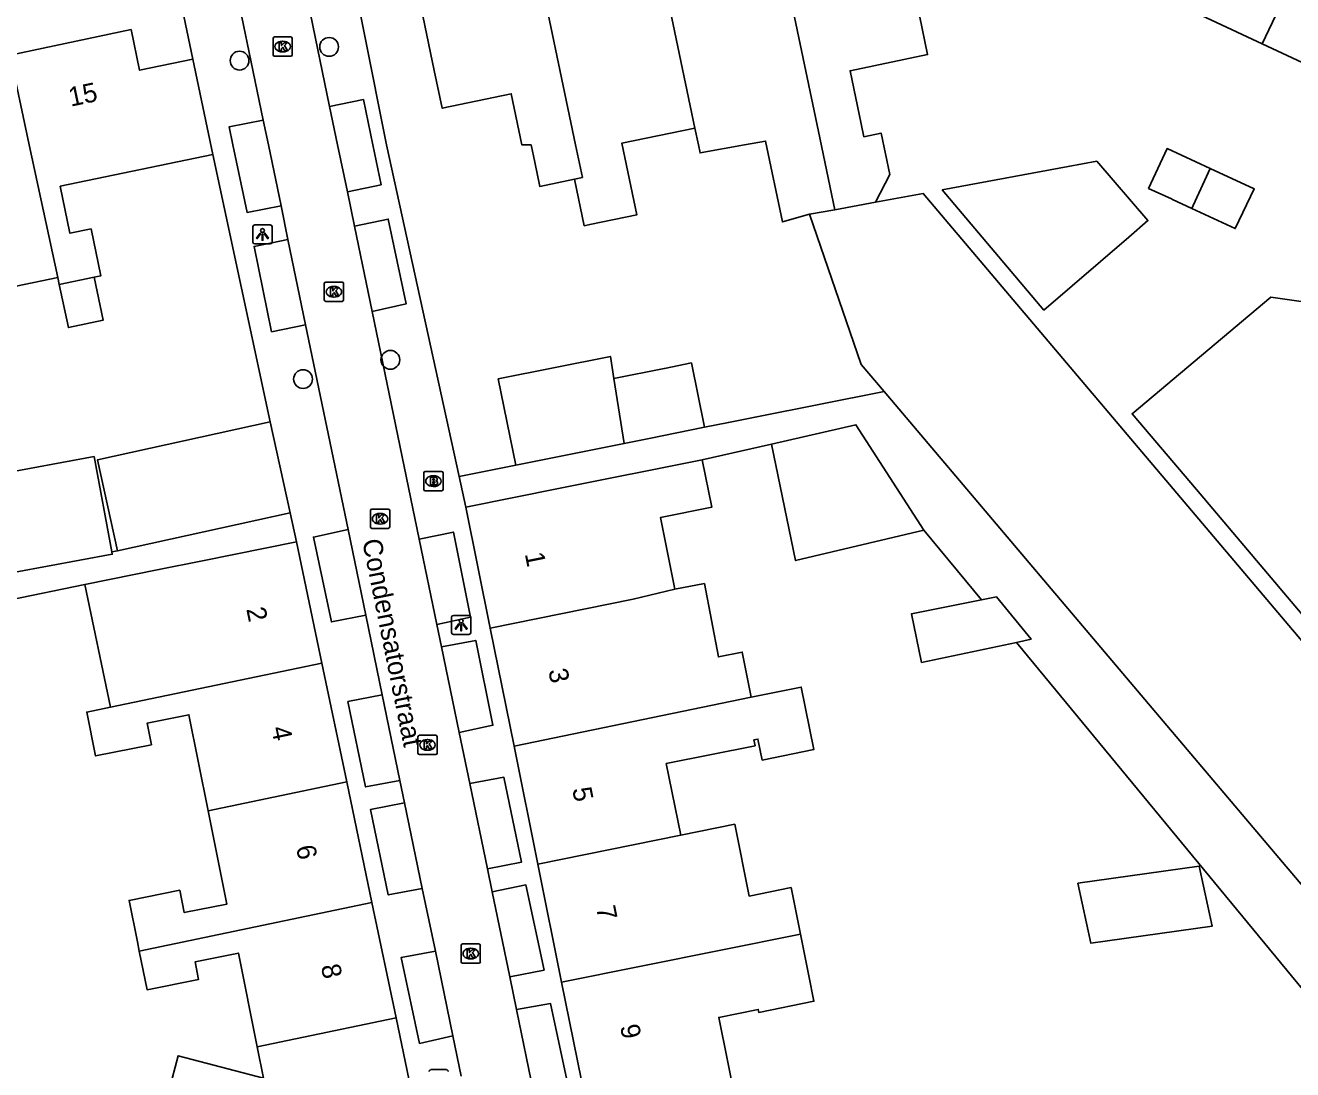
# Model space of a CAD drawing. Extents: x 162990 to 165007, y 383433 to 384336.
# Drawn here: x 163657.2 to 163723.1, y 383951.9 to 384006.2 of the extents above; entities that cross this region are included whole.
import ezdxf

# ---------------------------------------------------------------- set-up
doc = ezdxf.new("R2010")
doc.units = 0
for name, color, linetype in [('IMGEO_Boom', 7, 'Continuous'), ('IMGEO_Brandkraan', 7, 'Continuous'), ('IMGEO_Kolk', 7, 'Continuous'), ('IMGEO_Lichtpunt', 7, 'Continuous'), ('IMGEO_Openbare_ruimte_label', 7, 'Continuous'), ('IMGEO_Pand', 7, 'Continuous'), ('IMGEO_Pand_nummerreeks', 7, 'Continuous'), ('IMGEO_Rijbaan_lokaal_open', 7, 'Continuous'), ('IMGEO_Voetpad_open', 7, 'Continuous')]:
    doc.layers.add(name, color=color, linetype=linetype)

msp = doc.modelspace()

# ---------------------------------------------------------------- linework, layer by layer
at = {"layer": 'IMGEO_Boom'}
for centre in [(163673.01, 384005.098), (163668.353, 384004.381), (163676.194, 383988.817), (163671.653, 383987.815)]:
    msp.add_circle(centre, 0.489, dxfattribs=at)
at = {"layer": 'IMGEO_Brandkraan'}
for p, q in [((163677.934, 383982.078), (163677.934, 383982.93)), ((163678.009, 383983.004), (163678.861, 383983.004)), ((163678.422, 383982.784), (163678.447, 383982.784)), ((163678.935, 383982.93), (163678.935, 383982.078)), ((163678.445, 383982.224), (163678.42, 383982.224)), ((163678.861, 383982.004), (163678.009, 383982.004))]:
    msp.add_line(p, q, dxfattribs=at)
for points in [[(163677.934, 383982.078), (163677.934, 383982.93)], [(163678.009, 383983.004), (163678.861, 383983.004)], [(163678.935, 383982.93), (163678.935, 383982.078)], [(163678.282, 383982.704), (163678.282, 383982.304), (163678.495, 383982.304)], [(163678.513, 383982.704), (163678.282, 383982.704)], [(163678.461, 383982.623), (163678.407, 383982.623), (163678.407, 383982.547)], [(163678.407, 383982.547), (163678.46, 383982.547)], [(163678.469, 383982.471), (163678.407, 383982.471), (163678.407, 383982.39)], [(163678.407, 383982.39), (163678.469, 383982.39)], [(163678.861, 383982.004), (163678.009, 383982.004)]]:
    msp.add_lwpolyline(points, dxfattribs=at)
for centre, radius, start, end in [((163678.011, 383982.928), 0.0765, 91.55205, 178.44795), ((163678.011, 383982.928), 0.0765, 91.55205, 178.44795), ((163678.859, 383982.928), 0.0765, 1.55205, 88.44795), ((163678.859, 383982.928), 0.0765, 1.55205, 88.44795), ((163678.011, 383982.08), 0.0765, 181.55205, 268.44795), ((163678.011, 383982.08), 0.0765, 181.55205, 268.44795), ((163678.462, 383982.585), 0.0379, 267.82845, 90.93552), ((163678.47, 383982.43), 0.0404, 269.87594, 90.50774), ((163678.501, 383982.555), 0.251, 268.66757, 293.53466), ((163678.517, 383982.559), 0.145, 59.4692, 91.53667), ((163678.542, 383982.606), 0.0922, 285.51372, 58.15012), ((163678.547, 383982.414), 0.105, 301.31148, 78.98903), ((163678.859, 383982.08), 0.0765, 271.55205, 358.44795), ((163678.859, 383982.08), 0.0765, 271.55205, 358.44795)]:
    msp.add_arc(centre, radius, start, end, dxfattribs=at)
for centre, major_axis, ratio, start_param, end_param in [((163678.421, 383982.504), (-0.387, 0.002), 0.722429, 4.712389, 7.853982), ((163678.446, 383982.504), (-0.39, 0.002), 0.717154, 1.570796, 4.712389)]:
    msp.add_ellipse(centre, major_axis=major_axis, ratio=ratio, start_param=start_param, end_param=end_param, dxfattribs=at)
at = {"layer": 'IMGEO_Kolk'}
for p, q in [((163670.093, 384004.69), (163670.093, 384005.542)), ((163670.168, 384005.616), (163671.02, 384005.616)), ((163670.581, 384005.396), (163670.606, 384005.396)), ((163671.094, 384005.542), (163671.094, 384004.69)), ((163671.02, 384004.616), (163670.168, 384004.616)), ((163670.604, 384004.836), (163670.579, 384004.836)), ((163672.76, 383991.93), (163672.76, 383992.782)), ((163672.835, 383992.856), (163673.687, 383992.856)), ((163673.248, 383992.636), (163673.273, 383992.636)), ((163673.761, 383992.782), (163673.761, 383991.93)), ((163673.271, 383992.076), (163673.246, 383992.076)), ((163673.687, 383991.856), (163672.835, 383991.856)), ((163675.16, 383980.12), (163675.16, 383980.972)), ((163675.235, 383981.046), (163676.087, 383981.046)), ((163675.648, 383980.826), (163675.673, 383980.826)), ((163676.161, 383980.972), (163676.161, 383980.12)), ((163675.671, 383980.266), (163675.646, 383980.266)), ((163676.087, 383980.046), (163675.235, 383980.046)), ((163677.627, 383968.354), (163677.627, 383969.206)), ((163677.702, 383969.28), (163678.554, 383969.28)), ((163678.115, 383969.06), (163678.14, 383969.06)), ((163678.628, 383969.206), (163678.628, 383968.354)), ((163678.554, 383968.28), (163677.702, 383968.28)), ((163678.138, 383968.5), (163678.113, 383968.5)), ((163679.873, 383957.498), (163679.873, 383958.35)), ((163679.948, 383958.424), (163680.8, 383958.424)), ((163680.874, 383958.35), (163680.874, 383957.498)), ((163680.361, 383958.204), (163680.386, 383958.204)), ((163680.8, 383957.424), (163679.948, 383957.424)), ((163680.384, 383957.644), (163680.359, 383957.644))]:
    msp.add_line(p, q, dxfattribs=at)
for points in [[(163670.093, 384004.69), (163670.093, 384005.542)], [(163670.168, 384005.616), (163671.02, 384005.616)], [(163670.414, 384005.316), (163670.537, 384005.316), (163670.537, 384005.165), (163670.667, 384005.316), (163670.831, 384005.316), (163670.685, 384005.165), (163670.838, 384004.916), (163670.686, 384004.916), (163670.601, 384005.08), (163670.537, 384005.013), (163670.537, 384004.916), (163670.414, 384004.916), (163670.414, 384005.316)], [(163671.094, 384005.542), (163671.094, 384004.69)], [(163671.02, 384004.616), (163670.168, 384004.616)], [(163672.76, 383991.93), (163672.76, 383992.782)], [(163672.835, 383992.856), (163673.687, 383992.856)], [(163673.761, 383992.782), (163673.761, 383991.93)], [(163673.081, 383992.556), (163673.204, 383992.556), (163673.204, 383992.405), (163673.334, 383992.556), (163673.498, 383992.556), (163673.352, 383992.405), (163673.505, 383992.156), (163673.353, 383992.156), (163673.268, 383992.32), (163673.204, 383992.253), (163673.204, 383992.156), (163673.081, 383992.156), (163673.081, 383992.556)], [(163673.687, 383991.856), (163672.835, 383991.856)], [(163675.16, 383980.12), (163675.16, 383980.972)], [(163675.235, 383981.046), (163676.087, 383981.046)], [(163675.481, 383980.746), (163675.604, 383980.746), (163675.604, 383980.595), (163675.734, 383980.746), (163675.898, 383980.746), (163675.752, 383980.595), (163675.905, 383980.346), (163675.753, 383980.346), (163675.668, 383980.51), (163675.604, 383980.443), (163675.604, 383980.346), (163675.481, 383980.346), (163675.481, 383980.746)], [(163676.161, 383980.972), (163676.161, 383980.12)], [(163676.087, 383980.046), (163675.235, 383980.046)], [(163677.627, 383968.354), (163677.627, 383969.206)], [(163677.702, 383969.28), (163678.554, 383969.28)], [(163677.948, 383968.98), (163678.071, 383968.98), (163678.071, 383968.829), (163678.201, 383968.98), (163678.365, 383968.98), (163678.219, 383968.829), (163678.372, 383968.58), (163678.22, 383968.58), (163678.135, 383968.744), (163678.071, 383968.677), (163678.071, 383968.58), (163677.948, 383968.58), (163677.948, 383968.98)], [(163678.628, 383969.206), (163678.628, 383968.354)], [(163678.554, 383968.28), (163677.702, 383968.28)], [(163679.873, 383957.498), (163679.873, 383958.35)], [(163679.948, 383958.424), (163680.8, 383958.424)], [(163680.874, 383958.35), (163680.874, 383957.498)], [(163680.194, 383958.124), (163680.317, 383958.124), (163680.317, 383957.973), (163680.447, 383958.124), (163680.611, 383958.124), (163680.465, 383957.973), (163680.618, 383957.724), (163680.466, 383957.724), (163680.381, 383957.888), (163680.317, 383957.821), (163680.317, 383957.724), (163680.194, 383957.724), (163680.194, 383958.124)], [(163680.8, 383957.424), (163679.948, 383957.424)]]:
    msp.add_lwpolyline(points, dxfattribs=at)
for centre, start, end in [((163670.17, 384005.54), 91.55205, 178.44795), ((163670.17, 384005.54), 91.55205, 178.44795), ((163671.018, 384005.54), 1.55205, 88.44795), ((163671.018, 384005.54), 1.55205, 88.44795), ((163670.17, 384004.692), 181.55205, 268.44795), ((163670.17, 384004.692), 181.55205, 268.44795), ((163671.018, 384004.692), 271.55205, 358.44795), ((163671.018, 384004.692), 271.55205, 358.44795), ((163672.837, 383992.78), 91.55205, 178.44795), ((163672.837, 383992.78), 91.55205, 178.44795), ((163673.685, 383992.78), 1.55205, 88.44795), ((163673.685, 383992.78), 1.55205, 88.44795), ((163672.837, 383991.932), 181.55205, 268.44795), ((163672.837, 383991.932), 181.55205, 268.44795), ((163673.685, 383991.932), 271.55205, 358.44795), ((163673.685, 383991.932), 271.55205, 358.44795), ((163675.237, 383980.97), 91.55205, 178.44795), ((163675.237, 383980.97), 91.55205, 178.44795), ((163676.085, 383980.97), 1.55205, 88.44795), ((163676.085, 383980.97), 1.55205, 88.44795), ((163675.237, 383980.122), 181.55205, 268.44795), ((163675.237, 383980.122), 181.55205, 268.44795), ((163676.085, 383980.122), 271.55205, 358.44795), ((163676.085, 383980.122), 271.55205, 358.44795), ((163677.704, 383969.204), 91.55205, 178.44795), ((163677.704, 383969.204), 91.55205, 178.44795), ((163678.552, 383969.204), 1.55205, 88.44795), ((163678.552, 383969.204), 1.55205, 88.44795), ((163677.704, 383968.356), 181.55205, 268.44795), ((163677.704, 383968.356), 181.55205, 268.44795), ((163678.552, 383968.356), 271.55205, 358.44795), ((163678.552, 383968.356), 271.55205, 358.44795), ((163679.95, 383958.348), 91.55205, 178.44795), ((163679.95, 383958.348), 91.55205, 178.44795), ((163680.798, 383958.348), 1.55205, 88.44795), ((163680.798, 383958.348), 1.55205, 88.44795), ((163679.95, 383957.5), 181.55205, 268.44795), ((163679.95, 383957.5), 181.55205, 268.44795), ((163680.798, 383957.5), 271.55205, 358.44795), ((163680.798, 383957.5), 271.55205, 358.44795)]:
    msp.add_arc(centre, 0.0765, start, end, dxfattribs=at)
for centre, major_axis, ratio, start_param, end_param in [((163670.58, 384005.116), (-0.387, 0.002), 0.722429, 4.712389, 7.853982), ((163670.605, 384005.116), (-0.39, 0.002), 0.717154, 1.570796, 4.712389), ((163673.247, 383992.356), (-0.387, 0.002), 0.722429, 4.712389, 7.853982), ((163673.272, 383992.356), (-0.39, 0.002), 0.717154, 1.570796, 4.712389), ((163675.647, 383980.546), (-0.387, 0.002), 0.722429, 4.712389, 7.853982), ((163675.672, 383980.546), (-0.39, 0.002), 0.717154, 1.570796, 4.712389), ((163678.114, 383968.78), (-0.387, 0.002), 0.722429, 4.712389, 7.853982), ((163678.139, 383968.78), (-0.39, 0.002), 0.717154, 1.570796, 4.712389), ((163680.36, 383957.924), (-0.387, 0.002), 0.722429, 4.712389, 7.853982), ((163680.385, 383957.924), (-0.39, 0.002), 0.717154, 1.570796, 4.712389)]:
    msp.add_ellipse(centre, major_axis=major_axis, ratio=ratio, start_param=start_param, end_param=end_param, dxfattribs=at)
at = {"layer": 'IMGEO_Lichtpunt'}
for p, q in [((163669.045, 383995.746), (163669.045, 383994.939)), ((163669.045, 383995.746), (163669.045, 383994.939)), ((163669.947, 383995.841), (163669.139, 383995.841)), ((163669.947, 383995.841), (163669.139, 383995.841)), ((163670.041, 383994.939), (163670.041, 383995.746)), ((163670.041, 383994.939), (163670.041, 383995.746)), ((163669.139, 383994.845), (163669.947, 383994.845)), ((163669.139, 383994.845), (163669.947, 383994.845)), ((163680.282, 383975.521), (163679.474, 383975.521)), ((163680.282, 383975.521), (163679.474, 383975.521)), ((163679.38, 383975.426), (163679.38, 383974.619)), ((163679.38, 383975.426), (163679.38, 383974.619)), ((163680.376, 383974.619), (163680.376, 383975.426)), ((163680.376, 383974.619), (163680.376, 383975.426)), ((163679.474, 383974.525), (163680.282, 383974.525)), ((163679.474, 383974.525), (163680.282, 383974.525)), ((163679.112, 383951.885), (163678.304, 383951.885)), ((163679.112, 383951.885), (163678.304, 383951.885))]:
    msp.add_line(p, q, dxfattribs=at)
for points in [[(163669.419, 383995.41), (163669.458, 383995.382), (163669.27, 383995.12), (163669.232, 383995.147), (163669.419, 383995.41)], [(163669.521, 383995.362), (163669.568, 383995.362), (163669.568, 383995.04), (163669.521, 383995.04), (163669.521, 383995.362)], [(163669.631, 383995.382), (163669.669, 383995.409), (163669.856, 383995.147), (163669.817, 383995.119), (163669.631, 383995.382)], [(163679.754, 383975.09), (163679.793, 383975.062), (163679.605, 383974.8), (163679.567, 383974.827), (163679.754, 383975.09)], [(163679.856, 383975.042), (163679.903, 383975.042), (163679.903, 383974.72), (163679.856, 383974.72), (163679.856, 383975.042)], [(163679.966, 383975.062), (163680.004, 383975.089), (163680.191, 383974.827), (163680.152, 383974.799), (163679.966, 383975.062)]]:
    msp.add_lwpolyline(points, dxfattribs=at)
for centre in [(163669.544, 383995.544), (163679.879, 383975.224)]:
    msp.add_circle(centre, 0.0994, dxfattribs=at)
for centre, start, end in [((163669.139, 383995.746), 90, 180), ((163669.139, 383995.746), 90, 180), ((163669.947, 383995.746), 0, 90), ((163669.947, 383995.746), 0, 90), ((163669.139, 383994.939), 180, 270), ((163669.139, 383994.939), 180, 270), ((163669.947, 383994.939), 270, 0), ((163669.947, 383994.939), 270, 360), ((163679.474, 383975.426), 90, 180), ((163679.474, 383975.426), 90, 180), ((163680.282, 383975.426), 0, 90), ((163680.282, 383975.426), 0, 90), ((163679.474, 383974.619), 180, 270), ((163679.474, 383974.619), 180, 270), ((163680.282, 383974.619), 270, 0), ((163680.282, 383974.619), 270, 360), ((163678.304, 383951.79), 90, 180), ((163678.304, 383951.79), 90, 180), ((163679.112, 383951.79), 0, 90), ((163679.112, 383951.79), 0, 90)]:
    msp.add_arc(centre, 0.0946, start, end, dxfattribs=at)
at = {"layer": 'IMGEO_Pand'}
for points in [[(163695.897, 384012.947), (163702.124, 384014.248), (163702.256, 384013.731), (163706.048, 384014.561), (163707.064, 384009.666), (163707.217, 384008.926), (163703.434, 384008.139), (163703.716, 384006.728), (163704.139, 384004.698), (163700.108, 384003.857), (163700.686, 384001.095), (163700.826, 384000.426), (163701.714, 384000.612), (163702.167, 383998.45), (163701.43, 383997.012)], [(163721.541, 384005.265), (163725.248, 384013.067)], [(163699.309, 383996.628), (163698.459, 384000.693), (163695.897, 384012.947)], [(163689.776, 384011.667), (163692.033, 384000.876)], [(163685.774, 383998.218), (163683.964, 383997.839), (163683.701, 383999.098), (163683.512, 384000), (163683.041, 384000), (163682.485, 384002.657), (163678.892, 384001.905), (163678.481, 384003.872), (163677.392, 384009.079), (163683.656, 384010.388)], [(163685.774, 383998.218), (163686.182, 383998.304), (163685.827, 384000), (163683.656, 384010.388)], [(163715.998, 384007.86), (163721.541, 384005.265)], [(163665.922, 384004.457), (163663.151, 384003.88), (163662.711, 384005.995), (163656.426, 384004.673)], [(163727.744, 384002.36), (163721.541, 384005.265)], [(163656.426, 384004.673), (163657.409, 384000), (163658.895, 383993.098)], [(163666.955, 383999.493), (163665.922, 384004.457)], [(163692.033, 384000.876), (163688.225, 384000.08), (163689.018, 383996.363), (163686.566, 383995.85), (163686.282, 383995.791), (163685.774, 383998.218)], [(163698.002, 383996.392), (163696.584, 383995.995), (163695.706, 384000.196), (163694.62, 384000), (163692.304, 383999.582), (163692.216, 384000), (163692.033, 384000.876)], [(163660.787, 383993.11), (163661.134, 383993.182), (163660.627, 383995.63), (163659.53, 383995.403), (163659.023, 383997.851), (163666.955, 383999.493)], [(163717.884, 383996.69), (163716.87, 383997.159), (163716.817, 383997.184), (163715.629, 383997.734), (163716.588, 383999.807), (163718.84, 383998.765)], [(163712.946, 383999.146), (163715.596, 383996.063), (163714.595, 383995.202), (163710.185, 383991.408), (163704.894, 383997.652), (163711.452, 383998.869), (163712.946, 383999.146)], [(163718.84, 383998.765), (163717.954, 383996.842), (163717.884, 383996.69)], [(163718.84, 383998.765), (163721.128, 383997.706), (163720.137, 383995.647), (163717.884, 383996.69)], [(163701.43, 383997.012), (163703.909, 383997.461), (163732.007, 383964.256)], [(163698.002, 383996.392), (163699.309, 383996.628)], [(163699.309, 383996.628), (163701.43, 383997.012)], [(163701.884, 383987.16), (163700.685, 383988.577), (163698.002, 383996.392)], [(163658.895, 383993.098), (163656.322, 383992.565), (163655.913, 383994.538), (163652.306, 383993.79)], [(163658.895, 383993.098), (163658.97, 383992.734)], [(163658.97, 383992.734), (163659.452, 383990.497), (163661.265, 383990.887), (163660.787, 383993.11)], [(163660.787, 383993.11), (163658.97, 383992.734)], [(163732.705, 383964.822), (163718.113, 383982.065), (163714.771, 383986.014), (163721.979, 383992.083), (163728.787, 383991.097), (163735.501, 383990.125), (163738.208, 383987.065)], [(163682.712, 383983.332), (163681.808, 383987.821), (163687.64, 383988.996), (163687.821, 383987.842)], [(163687.821, 383987.842), (163690.442, 383988.369), (163690.459, 383988.371), (163691.855, 383988.652), (163692.528, 383985.309)], [(163687.821, 383987.842), (163688.349, 383984.467)], [(163732.007, 383964.256), (163725.748, 383958.959), (163701.884, 383987.16)], [(163662.003, 383978.874), (163660.958, 383983.61), (163669.94, 383985.593)], [(163670.986, 383980.857), (163669.94, 383985.593)], [(163696.019, 383984.426), (163700.411, 383985.439), (163703.944, 383979.959)], [(163688.349, 383984.467), (163689.65, 383984.729), (163692.528, 383985.309)], [(163682.712, 383983.332), (163688.349, 383984.467)], [(163696.019, 383984.426), (163697.272, 383978.372), (163703.944, 383979.959)], [(163656.674, 383977.764), (163655.732, 383982.848), (163660.79, 383983.785), (163661.71, 383978.82)], [(163680.125, 383981.149), (163685.027, 383982.137), (163692.412, 383983.618)], [(163690.996, 383976.883), (163690.244, 383980.612), (163692.91, 383981.149), (163692.412, 383983.618)], [(163670.986, 383980.857), (163662.003, 383978.874)], [(163680.125, 383981.149), (163681.392, 383974.86)], [(163661.71, 383978.82), (163661.732, 383978.702), (163656.674, 383977.764)], [(163671.32, 383979.343), (163666.419, 383978.358), (163664.156, 383977.903), (163660.309, 383977.13)], [(163672.636, 383973.04), (163671.32, 383979.343)], [(163660.309, 383977.13), (163661.643, 383970.744)], [(163681.392, 383974.86), (163688.818, 383976.356), (163690.996, 383976.883)], [(163694.965, 383971.271), (163694.494, 383973.612), (163693.255, 383973.362), (163692.532, 383977.174), (163690.996, 383976.883)], [(163706.943, 383976.322), (163703.29, 383975.594), (163703.824, 383973.072), (163708.761, 383974.117)], [(163708.761, 383974.117), (163709.514, 383974.277), (163707.72, 383976.477), (163706.943, 383976.322)], [(163681.392, 383974.86), (163682.629, 383968.718)], [(163661.643, 383970.744), (163672.636, 383973.04)], [(163673.928, 383966.857), (163672.636, 383973.04)], [(163691.295, 383964.077), (163690.543, 383967.808), (163695.164, 383968.738), (163695.103, 383969.043), (163695.314, 383969.086), (163695.534, 383967.995), (163698.218, 383968.536), (163697.562, 383971.794), (163694.965, 383971.271)], [(163694.965, 383971.271), (163682.629, 383968.718)], [(163661.643, 383970.744), (163660.408, 383970.486), (163660.865, 383968.209), (163663.769, 383968.792), (163663.544, 383969.912), (163665.72, 383970.349), (163666.724, 383965.353)], [(163682.629, 383968.718), (163683.866, 383962.577)], [(163666.724, 383965.353), (163673.928, 383966.857)], [(163675.239, 383960.58), (163673.928, 383966.857)], [(163666.724, 383965.353), (163667.698, 383960.504), (163665.477, 383960.058), (163665.243, 383961.221), (163662.605, 383960.691), (163663.037, 383958.543), (163663.136, 383958.052)], [(163697.52, 383958.936), (163697.033, 383961.354), (163694.86, 383960.917), (163694.108, 383964.649), (163691.295, 383964.077)], [(163683.866, 383962.577), (163691.295, 383964.077)], [(163683.866, 383962.577), (163685.103, 383956.435)], [(163711.946, 383961.582), (163712.624, 383958.467), (163718.938, 383959.358), (163718.26, 383962.474), (163711.946, 383961.582)], [(163663.136, 383958.052), (163675.239, 383960.58)], [(163676.49, 383954.588), (163675.239, 383960.58)], [(163697.52, 383958.936), (163685.103, 383956.435)], [(163694.173, 383950.124), (163693.271, 383954.603), (163695.326, 383955.017), (163695.357, 383954.864), (163698.224, 383955.442), (163697.957, 383956.769), (163697.52, 383958.936)], [(163663.136, 383958.052), (163663.54, 383956.04), (163666.225, 383956.579), (163666.041, 383957.495), (163668.295, 383957.948), (163669.273, 383953.081)], [(163685.103, 383956.435), (163686.34, 383950.294)], [(163669.273, 383953.081), (163676.49, 383954.588)], [(163676.227, 383947.087), (163677.26, 383950.901), (163676.49, 383954.588)], [(163669.273, 383953.081), (163669.603, 383951.438), (163665.153, 383952.612), (163664.53, 383950.25), (163665.382, 383950.025)]]:
    msp.add_lwpolyline(points, dxfattribs=at)
at = {"layer": 'IMGEO_Rijbaan_lokaal_open'}
for points in [[(163671.293, 384010.439), (163673.037, 384002.004)], [(163667.83, 384009.769), (163669.585, 384001.291)], [(163673.959, 383997.551), (163673.452, 384000), (163673.037, 384002.004)], [(163669.585, 384001.291), (163669.852, 384000), (163670.508, 383996.831)], [(163673.959, 383997.551), (163674.326, 383995.772)], [(163670.508, 383996.831), (163670.871, 383995.074)], [(163675.245, 383991.331), (163674.326, 383995.772)], [(163670.871, 383995.074), (163671.79, 383990.634)], [(163675.245, 383991.331), (163677.694, 383979.491)], [(163671.79, 383990.634), (163673.995, 383979.982)], [(163673.995, 383979.982), (163674.916, 383975.532)], [(163678.612, 383975.053), (163677.694, 383979.491)], [(163674.916, 383975.532), (163675.773, 383971.383)], [(163678.612, 383975.053), (163678.855, 383973.878)], [(163679.775, 383969.429), (163678.855, 383973.878)], [(163675.773, 383971.383), (163676.693, 383966.931)], [(163679.775, 383969.429), (163680.324, 383966.774)], [(163676.693, 383966.931), (163676.938, 383965.761)], [(163681.243, 383962.33), (163680.324, 383966.774)], [(163676.938, 383965.761), (163677.855, 383961.311)], [(163681.243, 383962.33), (163681.49, 383961.136)], [(163677.855, 383961.311), (163678.534, 383958.049)], [(163682.406, 383956.709), (163681.49, 383961.136)], [(163678.534, 383958.049), (163679.446, 383953.639)], [(163682.406, 383956.709), (163682.756, 383955.016)], [(163683.589, 383950.502), (163683.646, 383950.713), (163682.756, 383955.016)], [(163679.446, 383953.639), (163679.88, 383951.543)]]:
    msp.add_lwpolyline(points, dxfattribs=at)
at = {"layer": 'IMGEO_Voetpad_open'}
for points in [[(163673.714, 384011.504), (163675.998, 384000), (163679.774, 383982.752)], [(163665.922, 384004.457), (163664.838, 384009.691)], [(163673.037, 384002.004), (163674.799, 384002.359), (163675.287, 384000), (163675.715, 383997.927), (163673.959, 383997.551)], [(163670.508, 383996.831), (163668.746, 383996.489), (163668.003, 384000), (163667.806, 384000.931), (163669.585, 384001.291)], [(163669.94, 383985.593), (163666.955, 383999.493)], [(163674.326, 383995.772), (163676.084, 383996.14), (163677.009, 383991.723), (163675.245, 383991.331)], [(163671.79, 383990.634), (163670.02, 383990.28), (163669.11, 383994.717), (163670.871, 383995.074)], [(163692.528, 383985.309), (163693.775, 383985.56), (163695.163, 383985.839), (163701.884, 383987.16)], [(163692.412, 383983.618), (163696.019, 383984.426)], [(163679.774, 383982.752), (163682.712, 383983.332)], [(163679.774, 383982.752), (163680.125, 383981.149)], [(163671.32, 383979.343), (163670.986, 383980.857)], [(163674.916, 383975.532), (163673.129, 383975.176), (163672.196, 383979.597), (163673.995, 383979.982)], [(163677.694, 383979.491), (163679.474, 383979.854), (163680.366, 383975.43), (163678.612, 383975.053)], [(163703.944, 383979.959), (163706.943, 383976.322)], [(163661.71, 383978.82), (163662.003, 383978.874)], [(163628.83, 383972.006), (163630.513, 383969.212), (163631.374, 383970.769), (163656.443, 383976.322), (163660.309, 383977.13)], [(163678.855, 383973.878), (163680.633, 383974.215), (163681.526, 383969.806), (163679.775, 383969.429)], [(163708.761, 383974.117), (163725.688, 383953.588), (163725.833, 383952.83), (163723.51, 383949.486), (163721.218, 383948.694), (163709.01, 383938.569), (163701.572, 383932.108), (163701.301, 383931.192), (163701.864, 383930.754), (163707.39, 383935.603)], [(163676.693, 383966.931), (163674.904, 383966.6), (163673.988, 383971.033), (163675.773, 383971.383)], [(163680.324, 383966.774), (163682.102, 383967.099), (163683.02, 383962.686), (163681.243, 383962.33)], [(163677.855, 383961.311), (163676.086, 383960.979), (163675.169, 383965.423), (163676.938, 383965.761)], [(163681.49, 383961.136), (163683.248, 383961.496), (163684.188, 383957.065), (163682.406, 383956.709)], [(163679.446, 383953.639), (163677.719, 383953.253), (163676.761, 383957.728), (163678.534, 383958.049)], [(163682.756, 383955.016), (163684.531, 383955.321), (163685.479, 383950.868), (163683.589, 383950.502)]]:
    msp.add_lwpolyline(points, dxfattribs=at)

# ---------------------------------------------------------------- texts
at = {"layer": 'IMGEO_Openbare_ruimte_label'}
msp.add_text('Condensatorstraat', height=1, rotation=281.42232, dxfattribs=at).set_placement((163674.725, 383979.403))
at = {"layer": 'IMGEO_Pand_nummerreeks'}
for s, rotation, p in [('15', 11.87742, (163659.573, 384001.984)), ('1', 281.38847, (163683.184, 383978.719)), ('2', 281.79699, (163668.698, 383975.85)), ('3', 281.39019, (163684.405, 383972.66)), ('4', 281.79699, (163669.991, 383969.659)), ('5', 281.39019, (163685.648, 383966.489)), ('6', 281.79644, (163671.284, 383963.47)), ('7', 281.38847, (163686.891, 383960.318)), ('8', 281.79644, (163672.578, 383957.278)), ('9', 281.39019, (163688.134, 383954.147))]:
    msp.add_text(s, height=1, rotation=rotation, dxfattribs=at).set_placement(p)

doc.saveas('drawing.dxf')
